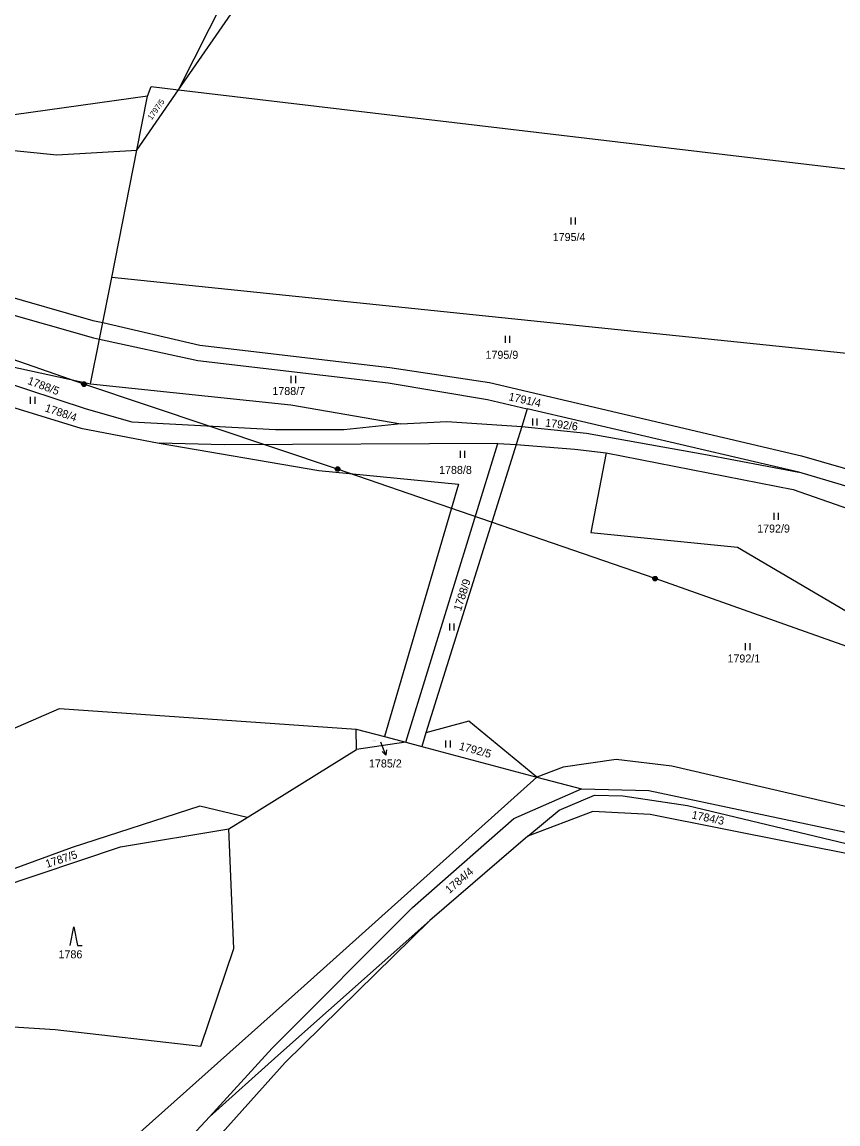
# Model space of a CAD drawing. Extents: x -609861 to -605046, y -1120287 to -1116307.
# Drawn here: x -609130.1 to -608956.9, y -1117954.9 to -1117720.7 of the extents above; entities that cross this region are included whole.
import ezdxf

# ---------------------------------------------------------------- set-up
doc = ezdxf.new("R2010")
doc.units = 0
for name, color, linetype in [('Vrstva 1', 7, 'Continuous'), ('Vrstva 2', 7, 'Continuous'), ('Vrstva 3', 7, 'Continuous'), ('Vrstva 6', 7, 'Continuous'), ('Vrstva 7', 7, 'Continuous')]:
    doc.layers.add(name, color=color, linetype=linetype)

msp = doc.modelspace()

# ---------------------------------------------------------------- linework, layer by layer
at = {"layer": 'Vrstva 1'}
for p, q in [((-609096.9, -1117735.12), (-609067.96, -1117677.82)), ((-609096.9, -1117735.12), (-609078.06, -1117707.9)), ((-609105.77, -1117747.94), (-609096.9, -1117735.12)), ((-609103.48, -1117736.49), (-609102.7, -1117734.43)), ((-609102.7, -1117734.43), (-609096.9, -1117735.12)), ((-609096.9, -1117735.12), (-608912.09, -1117757.04)), ((-609103.48, -1117736.49), (-609140.42, -1117741.63)), ((-609105.77, -1117747.94), (-609103.48, -1117736.49)), ((-609164.11, -1117744.68), (-609122.76, -1117748.93)), ((-609122.76, -1117748.93), (-609105.77, -1117747.94)), ((-609111.07, -1117774.96), (-609105.77, -1117747.94)), ((-609168.18, -1117769.05), (-609115.07, -1117784.1)), ((-609169.53, -1117772.34), (-609114.95, -1117787.8)), ((-609112.99, -1117784.58), (-609111.07, -1117774.96)), ((-608935.48, -1117793.2), (-609111.07, -1117774.96)), ((-609116.43, -1117802.97), (-609175.84, -1117783.44)), ((-609115.07, -1117784.1), (-609112.99, -1117784.58)), ((-609113.68, -1117788.08), (-609112.99, -1117784.58)), ((-609112.99, -1117784.58), (-609092.37, -1117789.34)), ((-609115.58, -1117797.61), (-609113.68, -1117788.08)), ((-609114.95, -1117787.8), (-609113.68, -1117788.08)), ((-609113.68, -1117788.08), (-609092.81, -1117792.66)), ((-609092.37, -1117789.34), (-609052.05, -1117794.13)), ((-609137.55, -1117792.83), (-609115.58, -1117797.61)), ((-609092.81, -1117792.66), (-609052.4, -1117797.35)), ((-609052.05, -1117794.13), (-609030.87, -1117797.32)), ((-609115.58, -1117797.61), (-609073.04, -1117802.04)), ((-609052.4, -1117797.35), (-609031.3, -1117800.94)), ((-609030.87, -1117797.32), (-608964.62, -1117812.86)), ((-609140.04, -1117800.1), (-609117.64, -1117807.01)), ((-609031.3, -1117800.94), (-609022.85, -1117802.91)), ((-609106.73, -1117805.77), (-609116.43, -1117802.97)), ((-609073.04, -1117802.04), (-609049.68, -1117806.12)), ((-609022.85, -1117802.91), (-609024.03, -1117806.69)), ((-608965.16, -1117816.33), (-609022.85, -1117802.91)), ((-609076.29, -1117807.36), (-609106.73, -1117805.77)), ((-609049.68, -1117806.12), (-609039.92, -1117805.59)), ((-609039.92, -1117805.59), (-609024.03, -1117806.69)), ((-609117.64, -1117807.01), (-609100.99, -1117810.19)), ((-609061.79, -1117807.33), (-609076.29, -1117807.36)), ((-609049.68, -1117806.12), (-609061.79, -1117807.33)), ((-609024.03, -1117806.69), (-609025.21, -1117810.45)), ((-609024.03, -1117806.69), (-609010.25, -1117808.07)), ((-609010.25, -1117808.07), (-608985.36, -1117812.5)), ((-609100.99, -1117810.19), (-609067.1, -1117816.04)), ((-609087.2, -1117810.55), (-609100.99, -1117810.19)), ((-609029.07, -1117810.28), (-609087.2, -1117810.55)), ((-609048.66, -1117873.74), (-609029.07, -1117810.28)), ((-609029.07, -1117810.28), (-609025.21, -1117810.45)), ((-609025.21, -1117810.45), (-609025.5, -1117811.38)), ((-609025.21, -1117810.45), (-609012.76, -1117811.48)), ((-609025.5, -1117811.38), (-609043.23, -1117868.13)), ((-609012.76, -1117811.48), (-609006.1, -1117812.27)), ((-609006.1, -1117812.27), (-609009.32, -1117829.16)), ((-609006.1, -1117812.27), (-608966.39, -1117820.02)), ((-608985.36, -1117812.5), (-608965.16, -1117816.33)), ((-608964.62, -1117812.86), (-608950.34, -1117816.99)), ((-609067.1, -1117816.04), (-609037.43, -1117818.88)), ((-608952.32, -1117820.16), (-608965.16, -1117816.33)), ((-609037.43, -1117818.88), (-609053.19, -1117872.53)), ((-608966.39, -1117820.02), (-608933.12, -1117831.74)), ((-609009.32, -1117829.16), (-608978.2, -1117832.33)), ((-608978.2, -1117832.33), (-608943, -1117853)), ((-609155.91, -1117881.2), (-609122.18, -1117866.61)), ((-609122.18, -1117866.61), (-609059.19, -1117870.94)), ((-609043.23, -1117868.13), (-609044.36, -1117871.76)), ((-609059.12, -1117875.29), (-609059.19, -1117870.94)), ((-609059.19, -1117870.94), (-609053.19, -1117872.53)), ((-609035.29, -1117869.29), (-609044.36, -1117871.76)), ((-609020.81, -1117881.14), (-609035.29, -1117869.29)), ((-609048.66, -1117873.74), (-609059.12, -1117875.29)), ((-609053.19, -1117872.53), (-609048.66, -1117873.74)), ((-609048.66, -1117873.74), (-609045.26, -1117874.64)), ((-609044.36, -1117871.76), (-609045.26, -1117874.64)), ((-609082.36, -1117889.76), (-609059.12, -1117875.29)), ((-609045.26, -1117874.64), (-609020.81, -1117881.14)), ((-609003.96, -1117877.43), (-609015.25, -1117879.01)), ((-608992.15, -1117878.82), (-609003.96, -1117877.43)), ((-609015.25, -1117879.01), (-609020.81, -1117881.14)), ((-608929.69, -1117893.32), (-608992.15, -1117878.82)), ((-609070.2, -1117925.5), (-609020.81, -1117881.14)), ((-609020.81, -1117881.14), (-609011.36, -1117883.65)), ((-609025.68, -1117889.96), (-609011.36, -1117883.65)), ((-609016.11, -1117888.15), (-609008.6, -1117884.97)), ((-609011.36, -1117883.65), (-608997.03, -1117884)), ((-609008.6, -1117884.97), (-609002.59, -1117885.17)), ((-609002.59, -1117885.17), (-608988.85, -1117887.16)), ((-608997.03, -1117884), (-608945.75, -1117894.9)), ((-609092.39, -1117887.34), (-609119.49, -1117896.1)), ((-609082.36, -1117889.76), (-609092.39, -1117887.34)), ((-608988.85, -1117887.16), (-608943.56, -1117898.09)), ((-609086.19, -1117892.15), (-609082.36, -1117889.76)), ((-609047.25, -1117908.88), (-609025.68, -1117889.96)), ((-609022.75, -1117893.73), (-609016.11, -1117888.15)), ((-609008.9, -1117888.48), (-609022.75, -1117893.73)), ((-608996.76, -1117889.1), (-609008.9, -1117888.48)), ((-608947.67, -1117898.92), (-608996.76, -1117889.1)), ((-609109.24, -1117895.99), (-609086.19, -1117892.15)), ((-609085.19, -1117917.61), (-609086.19, -1117892.15)), ((-609022.75, -1117893.73), (-609043.56, -1117911.61)), ((-609119.49, -1117896.1), (-609143.56, -1117904.9)), ((-609139.4, -1117906.07), (-609109.24, -1117895.99)), ((-609076.99, -1117938.76), (-609047.25, -1117908.88)), ((-609043.56, -1117911.61), (-609075.82, -1117940.32)), ((-609043.56, -1117911.61), (-609074.29, -1117941.83)), ((-609092.19, -1117938.36), (-609085.19, -1117917.61)), ((-609123.01, -1117972.59), (-609070.2, -1117925.5)), ((-609177.21, -1117931.59), (-609123.13, -1117934.76)), ((-609123.13, -1117934.76), (-609092.19, -1117938.36)), ((-609090.36, -1117953.31), (-609076.99, -1117938.76)), ((-609075.82, -1117940.32), (-609090.36, -1117953.31)), ((-609074.29, -1117941.83), (-609097.83, -1117968.07)), ((-609101.37, -1117965.28), (-609090.36, -1117953.31))]:
    msp.add_line(p, q, dxfattribs=at)
at = {"layer": 'Vrstva 3'}
for p, q in [((-609013.61, -1117762.23), (-609013.61, -1117763.73)), ((-609012.61, -1117763.73), (-609012.61, -1117762.23)), ((-609027.55, -1117787.41), (-609027.55, -1117788.91)), ((-609026.55, -1117788.91), (-609026.55, -1117787.41)), ((-609073.03, -1117795.92), (-609073.03, -1117797.42)), ((-609072.03, -1117797.42), (-609072.03, -1117795.92)), ((-609128.38, -1117800.33), (-609128.38, -1117801.83)), ((-609127.38, -1117801.83), (-609127.38, -1117800.33)), ((-609021.74, -1117804.94), (-609021.74, -1117806.44)), ((-609020.74, -1117806.44), (-609020.74, -1117804.94)), ((-609037.1, -1117811.82), (-609037.1, -1117813.32)), ((-609036.1, -1117813.32), (-609036.1, -1117811.82)), ((-608970.48, -1117824.97), (-608970.48, -1117826.47)), ((-608969.48, -1117826.47), (-608969.48, -1117824.97)), ((-609039.36, -1117848.49), (-609039.36, -1117849.99)), ((-609038.36, -1117849.99), (-609038.36, -1117848.49)), ((-608976.55, -1117852.67), (-608976.55, -1117854.17)), ((-608975.55, -1117854.17), (-608975.55, -1117852.67)), ((-609040.18, -1117873.39), (-609040.18, -1117874.89)), ((-609039.18, -1117874.89), (-609039.18, -1117873.39))]:
    msp.add_line(p, q, dxfattribs=at)
msp.add_lwpolyline([(-609119.89, -1117916.96), (-609119.14, -1117912.96), (-609118.39, -1117916.96), (-609117.39, -1117916.96)], dxfattribs=at)
at = {"layer": 'Vrstva 6'}
for p, q in [((-609116.98, -1117797.68), (-609176.69, -1117776.87)), ((-609063.12, -1117815.71), (-609116.98, -1117797.68)), ((-608995.72, -1117838.98), (-609063.12, -1117815.71)), ((-608927.09, -1117863.26), (-608995.72, -1117838.98))]:
    msp.add_line(p, q, dxfattribs=at)
for points in [[(-609117.13, -1117797.2), (-609116.82, -1117797.2), (-609116.57, -1117797.38), (-609116.47, -1117797.67), (-609116.57, -1117797.96), (-609116.82, -1117798.14), (-609117.13, -1117798.14), (-609117.38, -1117797.96), (-609117.48, -1117797.67), (-609117.38, -1117797.38), (-609117.13, -1117797.2), (-609117.1, -1117797.24), (-609116.86, -1117797.24), (-609116.7, -1117797.32), (-609117.26, -1117797.32), (-609117.34, -1117797.4), (-609116.62, -1117797.4), (-609116.62, -1117797.48), (-609117.34, -1117797.48), (-609117.38, -1117797.56), (-609116.58, -1117797.56), (-609116.54, -1117797.64), (-609117.42, -1117797.64), (-609117.42, -1117797.72), (-609116.54, -1117797.72), (-609116.57, -1117797.8), (-609117.38, -1117797.8), (-609117.37, -1117797.88), (-609116.56, -1117797.88), (-609116.61, -1117797.96), (-609117.33, -1117797.96), (-609117.25, -1117798.04), (-609116.69, -1117798.04), (-609116.8, -1117798.12), (-609117.14, -1117798.12)], [(-609063.27, -1117815.23), (-609062.96, -1117815.23), (-609062.71, -1117815.41), (-609062.61, -1117815.7), (-609062.71, -1117815.99), (-609062.96, -1117816.17), (-609063.27, -1117816.17), (-609063.52, -1117815.99), (-609063.62, -1117815.7), (-609063.52, -1117815.41), (-609063.27, -1117815.23), (-609063.24, -1117815.27), (-609063, -1117815.27), (-609062.84, -1117815.35), (-609063.4, -1117815.35), (-609063.48, -1117815.43), (-609062.76, -1117815.43), (-609062.76, -1117815.51), (-609063.48, -1117815.51), (-609063.52, -1117815.59), (-609062.72, -1117815.59), (-609062.68, -1117815.67), (-609063.56, -1117815.67), (-609063.56, -1117815.75), (-609062.68, -1117815.75), (-609062.71, -1117815.83), (-609063.52, -1117815.83), (-609063.51, -1117815.91), (-609062.7, -1117815.91), (-609062.75, -1117815.99), (-609063.47, -1117815.99), (-609063.39, -1117816.07), (-609062.83, -1117816.07), (-609062.94, -1117816.15), (-609063.28, -1117816.15)], [(-608995.87, -1117838.5), (-608995.56, -1117838.5), (-608995.31, -1117838.68), (-608995.21, -1117838.97), (-608995.31, -1117839.26), (-608995.56, -1117839.44), (-608995.87, -1117839.44), (-608996.12, -1117839.26), (-608996.22, -1117838.97), (-608996.12, -1117838.68), (-608995.87, -1117838.5), (-608995.84, -1117838.54), (-608995.6, -1117838.54), (-608995.44, -1117838.62), (-608996, -1117838.62), (-608996.08, -1117838.7), (-608995.36, -1117838.7), (-608995.36, -1117838.78), (-608996.08, -1117838.78), (-608996.12, -1117838.86), (-608995.32, -1117838.86), (-608995.28, -1117838.94), (-608996.16, -1117838.94), (-608996.16, -1117839.02), (-608995.28, -1117839.02), (-608995.31, -1117839.1), (-608996.12, -1117839.1), (-608996.11, -1117839.18), (-608995.3, -1117839.18), (-608995.35, -1117839.26), (-608996.07, -1117839.26), (-608995.99, -1117839.34), (-608995.43, -1117839.34), (-608995.54, -1117839.42), (-608995.88, -1117839.42)]]:
    msp.add_lwpolyline(points, dxfattribs=at)
at = {"layer": 'Vrstva 7'}
msp.add_line((-609052.852, -1117876.48), (-609053.98, -1117873.7), dxfattribs=at)
msp.add_lwpolyline([(-609052.765, -1117875.365), (-609052.852, -1117876.48), (-609053.691, -1117875.741)], dxfattribs=at)

# ---------------------------------------------------------------- texts
at = {"layer": 'Vrstva 2'}
for s, height, rotation, p in [('1797/5', 1.2, 54.88936, (-609102.611, -1117741.633)), ('1788/5', 1.7, 339.30561, (-609129.103, -1117797.579)), ('1791/4', 1.7, 347.38431, (-609026.927, -1117801.066)), ('1788/4', 1.7, 341.08178, (-609125.419, -1117803.387)), ('1792/6', 1.7, 352.82741, (-609019.12, -1117806.649)), ('1788/9', 1.7, 72.02079, (-609036.959, -1117845.996)), ('1792/5', 1.7, 344.69141, (-609037.461, -1117875.284)), ('1784/3', 1.7, 348.30104, (-608988.045, -1117889.93)), ('1787/5', 1.7, 17.99087, (-609124.847, -1117900.459)), ('1784/4', 1.7, 40.50812, (-609039.391, -1117906.015))]:
    msp.add_text(s, height=height, rotation=rotation, dxfattribs=at).set_placement(p)
for s, height, p in [('1795/4', 1.7, (-609017.447, -1117767.25)), ('1795/9', 1.7, (-609031.717, -1117792.27)), ('1788/7', 1.7, (-609076.977, -1117799.97)), ('1788/8', 1.7, (-609041.577, -1117816.73)), ('1792/9', 1.7, (-608974.037, -1117829.19)), ('1792/1', 1.7, (-608980.337, -1117856.8)), ('1785/2', 0.2, (-609055.894, -1117873.58)), ('1786', 1.7, (-609122.387, -1117919.66))]:
    msp.add_text(s, height=height, dxfattribs=at).set_placement(p)
at = {"layer": 'Vrstva 7'}
msp.add_text('1785/2', height=1.7, dxfattribs=at).set_placement((-609056.462, -1117879.11))

doc.saveas('drawing.dxf')
